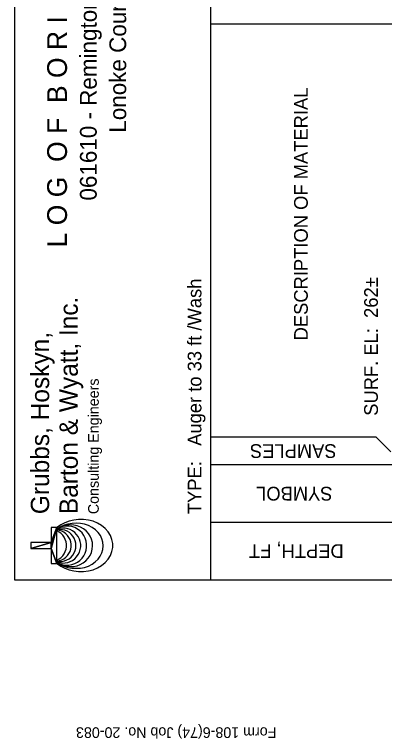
# Model space of a CAD drawing. Extents: x 1313964 to 1316843, y 2087046 to 2096619.
# Drawn here: x 1314075.31 to 1314089.05, y 2089812.81 to 2089839.67 of the extents above; entities that cross this region are included whole.
import ezdxf

# ---------------------------------------------------------------- set-up
doc = ezdxf.new("R2010")
doc.units = 0
doc.layers.add('B-Sub-Contour', color=7, linetype='Continuous')
doc.layers.add('Default', color=7, linetype='Continuous')

# ---------------------------------------------------------------- blocks, each defined once
blk = doc.blocks.new('DGRFC_GGHLOGO')
at = {"layer": 'Default'}
for points in [[(371581.68, 791230.32), (371581.68, 1050310.32), (295381.68, 1050310.32), (371581.68, 791230.32)], [(371581.68, 791230.32), (295381.68, 1050310.32), (295381.68, 791230.32), (371581.68, 791230.32)], [(295381.68, 791230.32), (104881.68, 791230.32), (104881.68, 715030.32), (295381.68, 791230.32)], [(295381.68, 791230.32), (104881.68, 715030.32), (562081.68, 715030.32), (295381.68, 791230.32)], [(295381.68, 791230.32), (562081.68, 715030.32), (371581.68, 791230.32), (295381.68, 791230.32)], [(562081.68, 715030.32), (562081.68, 791230.32), (371581.68, 791230.32), (562081.68, 715030.32)]]:
    blk.add_lwpolyline(points, close=True, dxfattribs=at)
for points in [[(105216.96, 715030.32), (100004.88, 709757.28), (68915.28, 666170.88), (42854.88, 615848.4), (22494.24, 560009.04), (8351.52, 500115.84), (792.48, 437662.32), (0, 374202.96), (7802.88, 311353.2), (23439.12, 250698), (46847.76, 193791.84), (77510.64, 142006.32), (114635.28, 96713.04), (157246.32, 59039.76), (204337.92, 29900.88), (254660.4, 10058.4), (306994.56, 0), (359968.8, 0), (412302.96, 10058.4), (462625.44, 29900.88), (509717.04, 59039.76), (552328.08, 96713.04), (589452.72, 142006.32), (620115.6, 193791.84), (643524.24, 250698), (659160.48, 311353.2), (666963.36, 374202.96), (666170.88, 437662.32), (658611.84, 500115.84), (644469.12, 560009.04), (624108.48, 615848.4), (598048.08, 666170.88), (566958.48, 709757.28), (561746.4, 715030.32)], [(111587.28, 715030.32), (108691.68, 711311.76), (85770.72, 670895.28), (67177.92, 625266.72), (53400.96, 575584.32), (44744.64, 523097.76), (41422.32, 469087.2), (42702.48, 414924.24), (52760.88, 362010.96), (69738.24, 311597.04), (93238.32, 264993.12), (122651.52, 223387.92), (157246.32, 187756.8), (196169.28, 159075.12), (238414.56, 137982.96), (282976.32, 125089.92), (328665.84, 120639.84), (374385.84, 124815.6), (419008.56, 137464.8), (461345.28, 158282.64), (500390.16, 186720.48), (535137.36, 222138.24), (564733.44, 263591.04), (588416.4, 310042.56), (605637.6, 360334.56), (615909.36, 413217.36), (618195.36, 467349.84), (615055.92, 521360.4), (606582.48, 573938.4), (592927.44, 623742.72), (574487.04, 669523.68), (551718.48, 710123.04), (547908.48, 715030.32)], [(113477.04, 715030.32), (111434.88, 712226.16), (91531.44, 674613.84), (76748.64, 633618.24), (67421.76, 590275.68), (63825.12, 545683.44), (65227.2, 500969.28), (74462.64, 457260.96), (90098.88, 415625.28), (111770.16, 377098.56), (138927.84, 342717.12), (170870.88, 313273.44), (206837.28, 289560), (245882.16, 272155.92), (287030.16, 261457.44), (329031.6, 257799.84), (371520.72, 261244.08), (412729.68, 271698.72), (451866, 288889.44), (487923.84, 312420), (520019.28, 341680.8), (547329.36, 375940.32), (569183.52, 414314.64), (585033.12, 455889.36), (594451.44, 499567.2), (596463.12, 544250.88), (593049.36, 588873.6), (583905.36, 632246.64), (569305.44, 673333.68), (549554.4, 711067.92), (546658.8, 715030.32)], [(117957.6, 715030.32), (116220.24, 712561.44), (98968.56, 677509.44), (87386.16, 640201.92), (81747.36, 601522.8), (82174.08, 562477.92), (88696.8, 523951.2), (101071.68, 486887.52), (119085.36, 452231.76), (142250.16, 420776.4), (170047.92, 393283.44), (201747.12, 370453.92), (236616.24, 352836.48), (273801.84, 340857.84), (312389.52, 334792.32), (351464.88, 334792.32), (390052.56, 340857.84), (427238.16, 352836.48), (462107.28, 370453.92), (493806.48, 393283.44), (521573.76, 420776.4), (544769.04, 452231.76), (562752.24, 486887.52), (575157.6, 523951.2), (581649.84, 562477.92), (582076.56, 601522.8), (576437.76, 640201.92), (564855.36, 677509.44), (547634.16, 712561.44), (545896.8, 715030.32)], [(124632.72, 715030.32), (123809.76, 713353.92), (113934.24, 680252.64), (109301.28, 646023.6), (110002.32, 611459.28), (116006.88, 577443.6), (127223.52, 544769.04), (143316.96, 514228.08), (163982.4, 486521.76), (188640.72, 462351.12), (216743.28, 442264.8), (247619.52, 426780.96), (280507.44, 416234.88), (314645.04, 410900.88), (349209.36, 410900.88), (383316.48, 416234.88), (416234.88, 426780.96), (447080.64, 442264.8), (475213.68, 462351.12), (499872, 486521.76), (520506.96, 514228.08), (536630.88, 544769.04), (547847.52, 577443.6), (553852.08, 611459.28), (554553.12, 646023.6), (549920.16, 680252.64), (540014.16, 713353.92), (539221.68, 715030.32)], [(130972.56, 715030.32), (130454.4, 713079.6), (127284.48, 680740.32), (129235.2, 648309.6), (136306.56, 616579.92), (148254.72, 586343.76), (164805.36, 558393.6), (185562.24, 533400), (210007.2, 511972.56), (237530.64, 494659.92), (267401.04, 481919.28), (298917.36, 474024.96), (331317.6, 471190.32), (363717.84, 473506.8), (395356.08, 480882.96), (425470.32, 493166.4), (453237.6, 510021.84), (478017.84, 531053.04), (499170.96, 555711.36), (516178.8, 583417.68), (528614.64, 613440.48), (536173.68, 645048.24), (538642.56, 677448.48), (535990.8, 709818.24), (534710.64, 715030.32)], [(135483.6, 715030.32), (135483.6, 714420.72), (140482.32, 683727.36), (150174.96, 654192.24), (164378.64, 626546.88), (182727.6, 601431.36), (204764.64, 579485.76), (229941.12, 561258.72), (257647.44, 547176.96), (287243.52, 537606.24), (317936.88, 532759.92), (349026.48, 532759.92), (379719.84, 537606.24), (409315.92, 547176.96), (437022.24, 561258.72), (462198.72, 579485.76), (484235.76, 601431.36), (502584.72, 626546.88), (516788.4, 654192.24), (526481.04, 683727.36), (531479.76, 714420.72), (531479.76, 715030.32)], [(146151.6, 715030.32), (160690.56, 687811.68), (179679.6, 662574.24), (202326.24, 640567.68), (228112.32, 622279.68), (256367.28, 608167.44), (286481.52, 598566.24), (317693.04, 593719.92), (349270.32, 593719.92), (380481.84, 598566.24), (410596.08, 608167.44), (438851.04, 622279.68), (464637.12, 640567.68), (487283.76, 662574.24), (506272.8, 687811.68), (520811.76, 715030.32)]]:
    blk.add_lwpolyline(points, dxfattribs=at)

msp = doc.modelspace()

# ---------------------------------------------------------------- linework, layer by layer
at = {"layer": 'B-Sub-Contour'}
for points in [[(1314136.725, 2089818.705), (1314136.725, 2089861.576), (1314075.306, 2089861.576), (1314075.306, 2089818.705), (1314136.725, 2089818.705)], [(1314082.603, 2089818.705), (1314082.603, 2089861.576)], [(1314134.292, 2089839.319), (1314082.603, 2089839.319)], [(1314088.745, 2089823.995), (1314082.603, 2089823.995)], [(1314089.292, 2089823.448), (1314088.745, 2089823.995)], [(1314134.292, 2089822.961), (1314082.603, 2089822.961)], [(1314134.292, 2089820.833), (1314082.603, 2089820.833)]]:
    msp.add_lwpolyline(points, dxfattribs=at)

# ---------------------------------------------------------------- block references
at = {"layer": 'B-Sub-Contour', "xscale": 2.894891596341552e-06, "yscale": 2.894891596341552e-06, "rotation": 90}
msp.add_blockref('DGRFC_GGHLOGO', (1314078.955, 2089819.009), dxfattribs=at)

# ---------------------------------------------------------------- texts
at = {"layer": 'B-Sub-Contour'}
for s, height, rotation, p in [('L O G  O F  B O R I N G  N O.  S2', 0.7352, 90, (1314077.257, 2089831.033)), ('061610 - Remington Road over I-40', 0.62209, 90, (1314078.361, 2089832.77)), ('Lonoke County, Arkansas', 0.62209, 90, (1314079.455, 2089835.288)), ('DESCRIPTION OF MATERIAL', 0.50899, 90, (1314086.202, 2089827.583)), ('TYPE:   Auger to 33 ft /Wash', 0.50899, 90, (1314082.25, 2089821.137)), ('SURF. EL:  262±', 0.50899, 90, (1314088.806, 2089824.786)), ('Barton & Wyatt, Inc.', 0.67865, 90, (1314077.657, 2089821.137)), ('Grubbs, Hoskyn,', 0.67865, 90, (1314076.593, 2089821.137)), ('Consulting Engineers', 0.39588, 90, (1314078.438, 2089821.137)), ('SAMPLES', 0.509, 180, (1314087.271, 2089823.733)), ('SYMBOL', 0.509, 180, (1314087.12, 2089822.152)), ('DEPTH, FT', 0.509, 180, (1314087.536, 2089820.023)), ('Form 108-6(74) Job No. 20-083', 0.39588, 180, (1314085.036, 2089813.232))]:
    msp.add_text(s, height=height, rotation=rotation, dxfattribs=at).set_placement(p)

doc.saveas('drawing.dxf')
